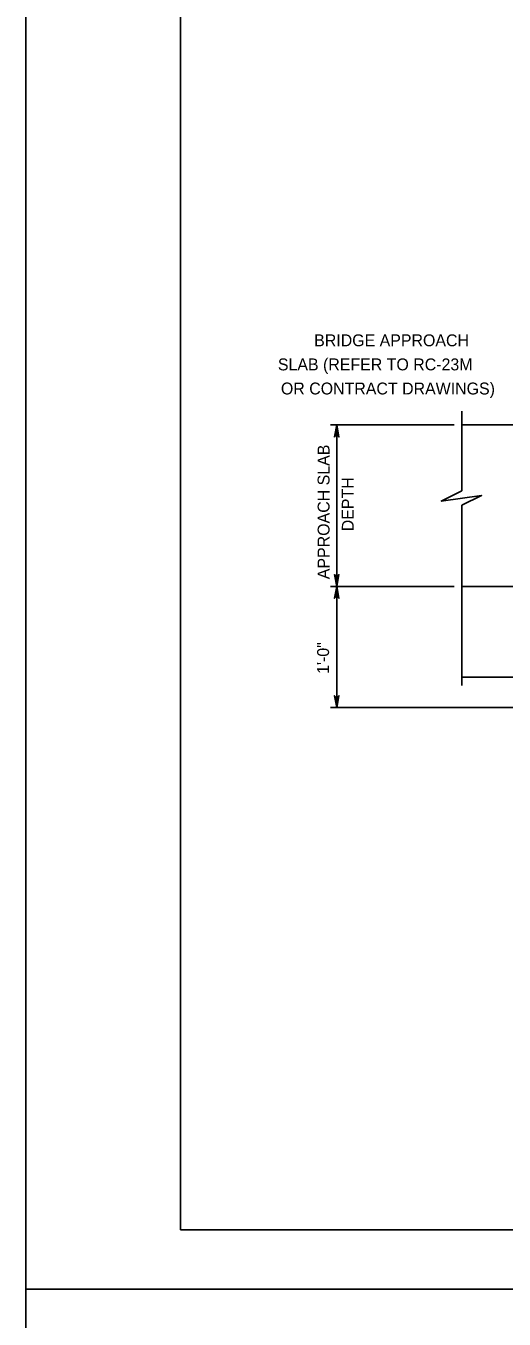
# Model space of a CAD drawing. Extents: x 2084213 to 2099800, y 976677 to 981262.
# Drawn here: x 2094075 to 2094470, y 978601 to 979670 of the extents above; entities that cross this region are included whole.
import ezdxf

# ---------------------------------------------------------------- set-up
doc = ezdxf.new("R2010")
doc.units = 0
doc.layers.add('1', color=7, linetype='Continuous')
doc.layers.add('PLT-BNDY', color=7, linetype='Continuous')

msp = doc.modelspace()

# ---------------------------------------------------------------- linework, layer by layer
at = {"layer": '1'}
for p, q in [((2094435.4, 979351.5), (2094435.4, 979285.5)), ((2094326.8, 979340), (2094429.1, 979340)), ((2094332, 979206.7), (2094332, 979340)), ((2094435.4, 979340), (2094902.4, 979340)), ((2094435.4, 979273.9), (2094435.4, 979124.9)), ((2094326.8, 979206.7), (2094429.1, 979206.7)), ((2094332, 979106.7), (2094332, 979206.7)), ((2094435.4, 979206.7), (2094902.4, 979206.7)), ((2094435.4, 979131.7), (2094502.4, 979131.7)), ((2094326.8, 979106.7), (2094644.9, 979106.7)), ((2094074.9, 978626.1), (2094074.9, 978626.1))]:
    msp.add_line(p, q, dxfattribs=at)
for points in [[(2096781.6, 978675.3), (2096781.6, 980525.7), (2094202.9, 980525.7), (2094202.9, 978675.3), (2096781.6, 978675.3), (2096781.6, 978761.8), (2096125.4, 978761.8), (2096125.4, 978974), (2096781.6, 978974), (2096781.6, 979069), (2096125.4, 979069), (2096125.4, 978675.3), (2096384, 978675.3), (2096384, 978761.8), (2096384, 978675.3), (2096636.6, 978675.3), (2096636.6, 978761.8), (2096636.6, 978721.4), (2096781.6, 978721.4)], [(2094332, 979340), (2094333.8, 979330.2), (2094333.3, 979331), (2094332.6, 979331.3), (2094332, 979331.5), (2094331.3, 979331.3), (2094330.7, 979331), (2094330.1, 979330.2), (2094332, 979340), (2094330.7, 979331), (2094331.3, 979331.3), (2094332, 979340), (2094332, 979331.5), (2094332.6, 979331.3), (2094332, 979340), (2094333.3, 979331)], [(2094435.4, 979285.5), (2094418.4, 979277.1), (2094451.7, 979281.7), (2094435.4, 979273.9)], [(2094332, 979206.7), (2094330.1, 979216.4), (2094330.7, 979215.7), (2094331.3, 979215.3), (2094332, 979215.2), (2094332.6, 979215.3), (2094333.3, 979215.7), (2094333.8, 979216.4), (2094332, 979206.7), (2094333.3, 979215.7), (2094332.6, 979215.3), (2094332, 979206.7), (2094332, 979215.2), (2094331.3, 979215.3), (2094332, 979206.7), (2094330.7, 979215.7)], [(2094332, 979206.7), (2094333.8, 979196.9), (2094333.3, 979197.6), (2094332.6, 979198), (2094332, 979198.1), (2094331.3, 979198), (2094330.7, 979197.6), (2094330.1, 979196.9), (2094332, 979206.7), (2094330.7, 979197.6), (2094331.3, 979198), (2094332, 979206.7), (2094332, 979198.1), (2094332.6, 979198), (2094332, 979206.7), (2094333.3, 979197.6)], [(2094332, 979106.7), (2094330.1, 979116.4), (2094330.7, 979115.7), (2094331.3, 979115.3), (2094332, 979115.2), (2094332.6, 979115.3), (2094333.3, 979115.7), (2094333.8, 979116.4), (2094332, 979106.7), (2094333.3, 979115.7), (2094332.6, 979115.3), (2094332, 979106.7), (2094332, 979115.2), (2094331.3, 979115.3), (2094332, 979106.7), (2094330.7, 979115.7)], [(2094332, 979106.7), (2094330.1, 979116.4), (2094330.7, 979115.7), (2094331.3, 979115.3), (2094332, 979115.2), (2094332.6, 979115.3), (2094333.3, 979115.7), (2094333.8, 979116.4), (2094332, 979106.7), (2094333.3, 979115.7), (2094332.6, 979115.3), (2094332, 979106.7), (2094332, 979115.2), (2094331.3, 979115.3), (2094332, 979106.7), (2094330.7, 979115.7)]]:
    msp.add_lwpolyline(points, dxfattribs=at)
at = {"layer": 'PLT-BNDY'}
for points in [[(2094074.9, 980574.9), (2096834.1, 980574.9), (2096834.1, 978626.1), (2094074.9, 978626.1)], [(2094074.9, 978626.1), (2096834.1, 978626.1), (2096834.1, 976677.3), (2094074.9, 976677.3)]]:
    msp.add_lwpolyline(points, close=True, dxfattribs=at)

# ---------------------------------------------------------------- texts
at = {"layer": '1'}
for s, p in [('BRIDGE APPROACH', (2094313.3, 979405)), ('SLAB (REFER TO RC-23M', (2094283.3, 979385.1)), ('OR CONTRACT DRAWINGS)', (2094285.8, 979365.2))]:
    msp.add_text(s, height=9.843, dxfattribs=at).set_placement(p)
for s, height, p in [('APPROACH SLAB', 9.843, (2094326, 979212.6)), ('DEPTH', 9.84, (2094346, 979252.2)), ('1\'-0"', 9.84, (2094325.6, 979134.4))]:
    msp.add_text(s, height=height, rotation=90, dxfattribs=at).set_placement(p)

doc.saveas('drawing.dxf')
